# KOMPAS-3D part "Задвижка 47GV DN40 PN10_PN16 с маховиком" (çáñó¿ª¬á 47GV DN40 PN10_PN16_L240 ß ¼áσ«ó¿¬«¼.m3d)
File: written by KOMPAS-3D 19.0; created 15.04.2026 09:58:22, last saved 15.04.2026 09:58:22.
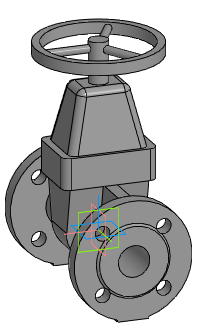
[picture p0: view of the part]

Document properties: Автор: Евгений; Полное имя файла: Z:\3.Личные\kachalov\3d для проектировщиков\2.1 Тип 47GV, 47GV.Z\Задвижка 47GV_DN40-DN600\stp_Задвижка 47GV\Задвижка 47GV DN40 PN10_PN16_L240 с маховиком.m3d

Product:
- Part/product: Задвижка 47GV DN40 PN10_PN16 с маховиком

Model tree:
1. Операция без истории:1  (labels: Задвижка 47GV DN40 PN10_PN16 с маховиком)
